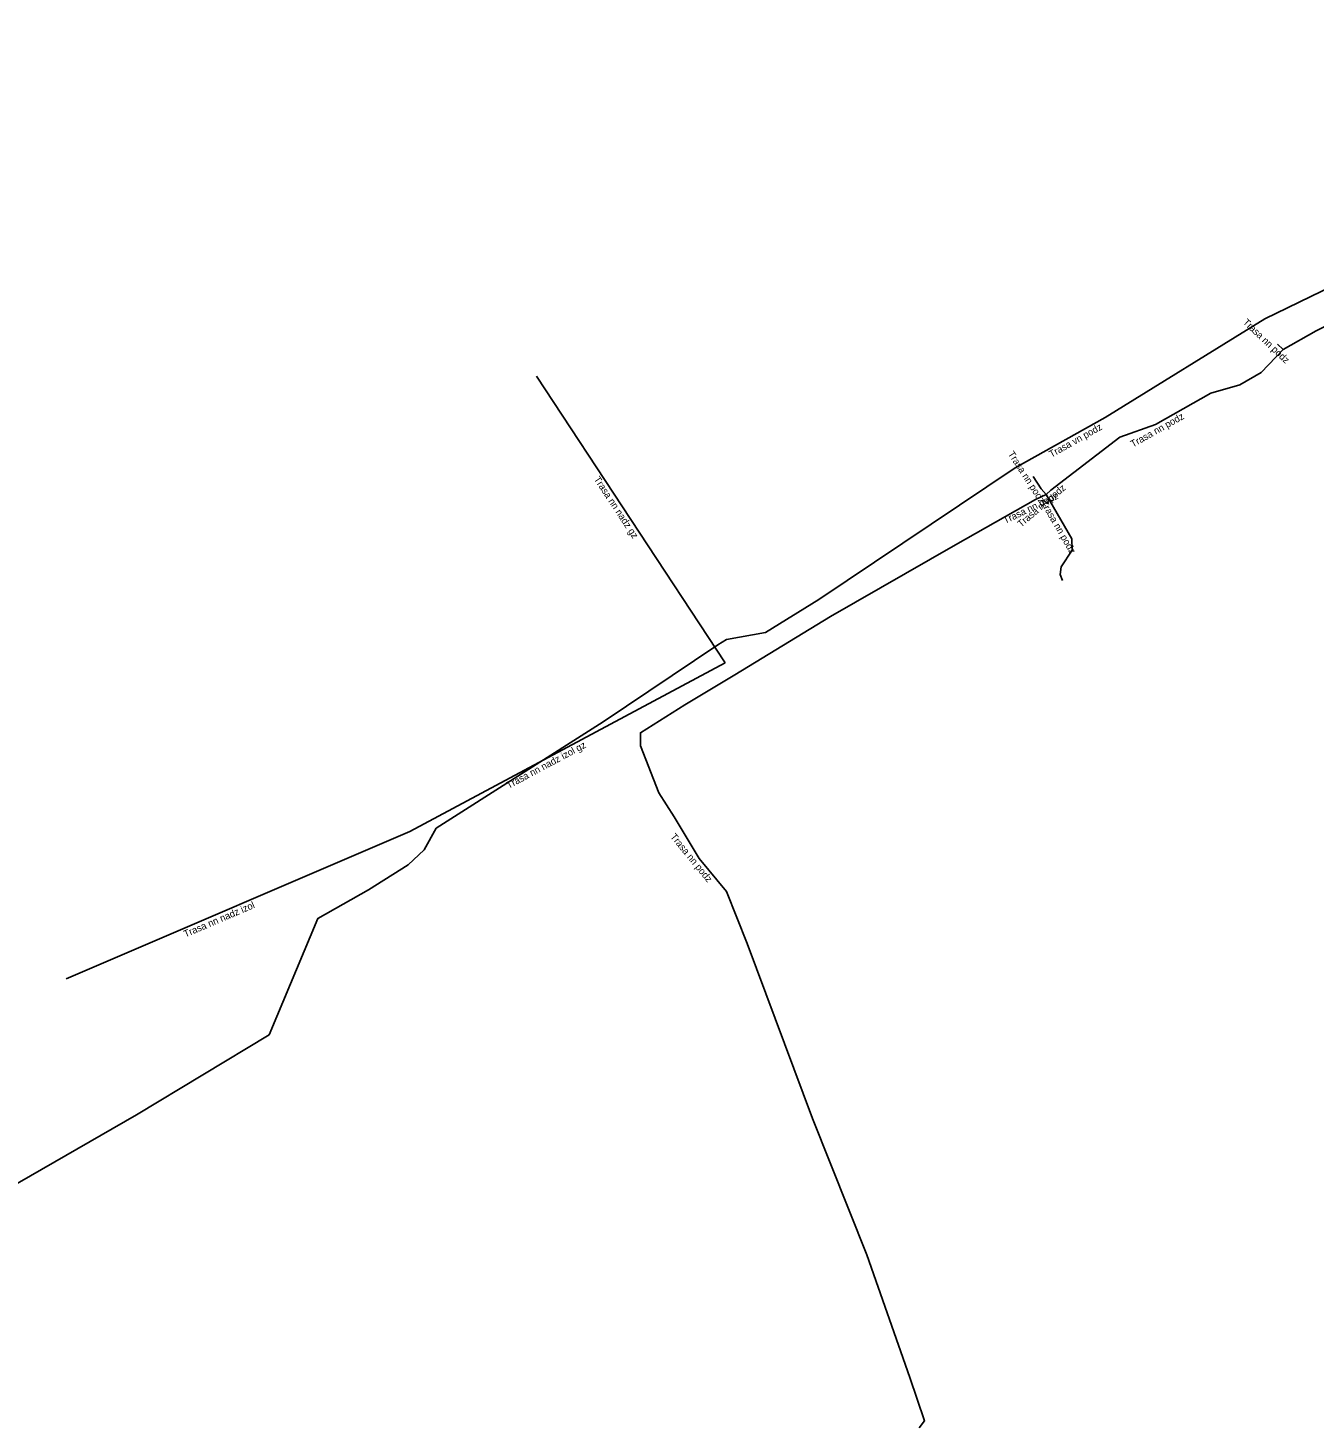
# Model space of a CAD drawing. Extents: x -691765 to -691141, y -976282 to -975901.
# Drawn here: x -691644.3 to -691552, y -976211 to -976110.6 of the extents above; entities that cross this region are included whole.
import ezdxf

# ---------------------------------------------------------------- set-up
doc = ezdxf.new("R2010")
doc.units = 0
for name, color, linetype in [('Popiskový text - Ostatní atributy Trasy', 7, 'Continuous'), ('Spojnice NN', 7, 'Continuous'), ('Spojnice VN', 7, 'Continuous')]:
    doc.layers.add(name, color=color, linetype=linetype)

msp = doc.modelspace()

# ---------------------------------------------------------------- linework, layer by layer
at = {"layer": 'Spojnice NN'}
for points in [[(-691523.88, -976118.24), (-691534.87, -976123.97), (-691536.44, -976125.13), (-691539.21, -976125.93), (-691541.84, -976126.83), (-691544.21, -976127.98), (-691548.67, -976130.73), (-691551.86, -976132.33), (-691554.22, -976133.66)], [(-691554.22, -976133.66), (-691554.62, -976133.28)], [(-691554.22, -976133.66), (-691555.79, -976135.32), (-691557.34, -976136.2), (-691559.41, -976136.81), (-691563.38, -976139.05), (-691565.95, -976139.97), (-691570.88, -976143.76)], [(-691607.78, -976135.59), (-691594.26, -976156.14)], [(-691572.16, -976142.78), (-691571.59, -976143.66), (-691571.23, -976144.06)], [(-691571.98, -976144.42), (-691577.74, -976147.69), (-691586.69, -976152.83), (-691593.57, -976157), (-691597.16, -976159.16), (-691600.33, -976161.16), (-691600.33, -976162.09), (-691599.02, -976165.47), (-691597.91, -976167.19), (-691596.11, -976170.18), (-691594.17, -976172.55), (-691592.68, -976176.27), (-691588, -976188.82), (-691584.1, -976198.62), (-691581, -976207.41), (-691579.96, -976210.52), (-691580.33, -976211.03)], [(-691571.23, -976144.06), (-691571.98, -976144.42)], [(-691571.23, -976144.06), (-691570.88, -976143.76)], [(-691571.23, -976144.06), (-691569.39, -976147.25), (-691569.36, -976148.07), (-691570.14, -976149.27), (-691570.22, -976149.82), (-691570.05, -976150.25)], [(-691616.87, -976168.24), (-691594.26, -976156.14)], [(-691641.54, -976178.8), (-691616.87, -976168.24)]]:
    msp.add_lwpolyline(points, dxfattribs=at)
at = {"layer": 'Spojnice VN'}
for points in [[(-691619.85, -976172.43), (-691616.99, -976170.64), (-691615.85, -976169.55), (-691614.99, -976168.01), (-691603, -976160.37), (-691594.79, -976154.85), (-691594.15, -976154.48), (-691591.37, -976153.98), (-691587.54, -976151.61), (-691573.45, -976142.15), (-691567, -976138.54), (-691555.53, -976131.47), (-691548.99, -976128.3), (-691533.7, -976120.79), (-691523.51, -976115.65), (-691513.94, -976110.61)], [(-691650.94, -976196.87), (-691636.48, -976188.57), (-691626.96, -976182.82), (-691623.49, -976174.48), (-691619.85, -976172.43)]]:
    msp.add_lwpolyline(points, dxfattribs=at)

# ---------------------------------------------------------------- texts
at = {"layer": 'Popiskový text - Ostatní atributy Trasy'}
for s, rotation, p in [('Trasa nn podz', 316.4688, (-691557.15, -976131.77)), ('Trasa nn podz', 29.4331, (-691565, -976140.71)), ('Trasa vn podz', 29.2353, (-691570.85, -976141.44)), ('Trasa nn podz', 302.9322, (-691573.99, -976141.16)), ('Trasa nn nadz gz', 303.3412, (-691603.7, -976142.97)), ('Trasa nn podz', 40.6013, (-691573.02, -976146.45)), ('Trasa nn podz', 25.641, (-691574.16, -976146.19)), ('Trasa nn podz', 299.9765, (-691571.63, -976144.67)), ('Trasa nn nadz izol gz', 28.154, (-691609.79, -976165.19)), ('Trasa nn podz', 309.3026, (-691598.22, -976168.63)), ('Trasa nn nadz izol', 23.1834, (-691632.98, -976175.85))]:
    msp.add_text(s, height=0.5, rotation=rotation, dxfattribs=at).set_placement(p)

doc.saveas('drawing.dxf')
